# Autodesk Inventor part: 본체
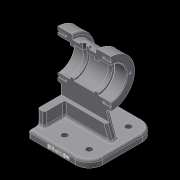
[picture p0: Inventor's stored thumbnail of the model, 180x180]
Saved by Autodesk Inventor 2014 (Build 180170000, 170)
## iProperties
Created: 2020-06
Part Number: 본체
Material: Generic
Document SubType Name: Modeling
Designer: kh
Density: 1 g/cm^3
Appearance: Default
Author: kh
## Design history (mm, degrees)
sketch "Sketch1"
  geometry: 1 further point
sketch "Sketch2"
  geometry: L1 (-45, 49)-(45, 49); L2 (45, 49)-(45, -49); L3 (45, -49)-(-45, -49); L4 (-45, -49)-(-45, 49); L5 (-45, 49)-(45, -49); L6 (45, 49)-(-45, -49); 1 further point
  constraints: 12 end point, 2 midpoint, 2 parallel, 1 horizontal, 1 perpendicular
  dimensions: "d0" = 90 distance of L1.start L1.end; "d1" = 98 distance of L1.end L2.end
extrude "Extrusion1" new body sketch "Sketch2" distance "d2" = 10; taper "d3" = 0 deg
sketch "Sketch4"
  geometry: L1 (-50, 105)-(-50, 70); L2 (-50, 70)-(28, 70); L3 (28, 70)-(28, 105); L4 (28, 105)-(6, 105); L5 (6, 105)-(6, 98.5); L6 (6, 98.5)-(-28, 98.5); L7 (-28, 98.5)-(-28, 105); L8 (-28, 105)-(-50, 105); L9 (-45, -10)-(45, -10) reference; 3 further points
  constraints: 16 end point, 4 parallel, 2 midpoint, 1 horizontal alignment, 1 perpendicular, 1 vertical
  dimensions: "d5" = 78 distance of L3.end L1.start; "d9" = 22 distance of L7.end L1.start; "d10" = 22 distance of L3.end L4.end; "d11" = 5 horizontal distance of L9.start L1.end; "d12" = 70 diameter of L8 L2; "d13" = 57 diameter of L6 L2; "d14" = 80 vertical distance of L9.end L2.end
revolve "Revolution1" sketch "Sketch4" stored, may be unused: angle "d15" = 90 deg
sketch "Sketch5"
  geometry: L1 (-45, 61.811)-(-45, 0); L2 (10.503, 61.811)-(33, 0); L3 (-45, 0)-(45, 0) reference; L4 (-45, 61.811)-(10.503, 61.811); L5 (-45, 0)-(33, 0); L6 (-50, 35)-(-50, 105) reference; 1 further point
  constraints: 8 end point, 2 point on line, 1 parallel, 1 perpendicular, 1 vertical
  dimensions: "d16" = 70 deg angle of L2 L3; "d17" = 5 distance from line of L1.end L6; "d18" = 12 distance of L3.end L2.end
extrude "Extrusion2" join sketch "Sketch5" stored distance "d19" = 10; taper "d20" = 0 deg
sketch "Sketch6"
  geometry: L1 (-45, 35)-(-35, 35); L2 (-35, 35)-(-35, -35); L3 (-35, -35)-(-45, -35); L4 (-45, -35)-(-45, 35); 3 further points
  constraints: 8 end point, 2 parallel, 1 horizontal, 1 horizontal alignment, 1 midpoint, 1 perpendicular, 1 vertical alignment
  dimensions: "d21" = 70 distance between parallel lines of L3 L1; "d22" = 10 horizontal distance of point (-45, 49) L1.end
extrude "Extrusion3" join sketch "Sketch6" distance "d23" = 70; taper "d24" = 0 deg
sketch "Sketch7"
  geometry: L1 (45, 49)-(45, -49) reference; 8 further points
  constraints: 3 horizontal alignment, 2 vertical alignment, 1 midpoint
  dimensions: "d25" = 36 distance of point (25, 29) point (-11, 29); "d26" = 70 horizontal distance of point (25, 29) point (-45, 49); "d27" = 58 distance of point (25, -29) point (25, 29)
hole "Hole1" sketch "Sketch7" at (-11, 29), (25, 29), (25, -29), (-11, -29) diameter "d28" = 9; stored, may be unused: countersink angle "d32" = 90 deg, drill point angle "d34" = 118 deg; dims "d29" = 6, "d30" = 4, "d31" = 2, "d33" = 8
sketch "Sketch8"
  geometry: L1 (-50, 70)-(28, 70); L2 (-50, 35)-(-50, 105) reference; L3 (28, 35)-(28, 105) reference; L4 (-50, 70)-(-50, 93.5); L5 (-50, 93.5)-(-32, 93.5); L6 (-32, 93.5)-(-32, 90); L7 (-32, 90)-(-26, 90); L8 (-26, 90)-(-26, 93); L9 (-26, 93)-(4, 93); L10 (4, 93)-(4, 90); L11 (4, 90)-(10, 90); L12 (10, 90)-(10, 93.5); L13 (10, 93.5)-(28, 93.5); L14 (28, 70)-(28, 93.5); 4 further points
  constraints: 24 end point, 6 parallel, 5 midpoint, 4 perpendicular, 3 point on line, 1 horizontal, 1 horizontal alignment
  dimensions: "d35" = 47 diameter of L5 L1; "d36" = 40 diameter of L7 L1; "d37" = 18 distance of L4.end L5.end; "d38" = 6 distance of L6.end L7.end; "d39" = 30 distance of L8.end L9.end; "d40" = 18 distance of L12.end L13.end; "d41" = 47 diameter of L13 L1; "d42" = 46 diameter of L9 L1
revolve "Revolution2" sketch "Sketch8" stored, may be unused: angle "d43" = 90 deg
workplane "Work Plane2"
sketch "Sketch9"
  geometry: L1 (-50, -35)-(-50, 35) reference; C1 r 6 at (-11, 0); 2 further points
  constraints: 1 centre point, 1 coincident, 1 horizontal alignment
  dimensions: "d45" = 39 distance from line of point (-11, 0) L1; "d46" = 12 diameter of C1
extrude "Extrusion4" join sketch "Sketch9" stored distance "d47" = 70; taper "d48" = 0 deg
hole "Hole2" diameter "d51" = 5.188; stored, may be unused: countersink angle "d55" = 90 deg, drill point angle "d57" = 118 deg; dims "d49" = 10, "d50" = 10, "d52" = 6, "d53" = 4, "d54" = 2, "d56" = 8
sketch "Sketch10"
  geometry: C1 r 23.5 at (0, 0) reference; 2 further points
  constraints: 1 vertical alignment
  dimensions: "d59" = 28.5 distance of C1.centre point (0, 28.5)
hole "Hole3" sketch "Sketch10" at (0, 28.5) diameter "d60" = 3.242; stored, may be unused: countersink angle "d64" = 90 deg, drill point angle "d66" = 118 deg; dims "d61" = 10, "d62" = 4, "d63" = 2, "d65" = 12
pattern_circular "Circular Pattern1" dims angle "d68" = 360 deg
workplane "Work Plane3"
mirror "Mirror1"
fillet "Fillet1" dims "d70" = 3
fillet "Fillet2" dims "d71" = 3
fillet "Fillet5" dims "d74" = 3
sketch "Sketch11"
  geometry: L1 (-3, 7)-(-3, 0) reference; 3 further points
  constraints: 1 other
  dimensions: "d75" = 4 vertical distance of point (0, 0) point (42, 4); "d76" = 45 distance from line of point (42, 4) L1
emboss "Emboss1" sketch "Sketch11" dims "d0" = 90, "d1" = 98, "d15" = 90 deg, "d77" = 0.5, "d78" = 0
chamfer "Chamfer1" distance "d79" = 1; stored, may be unused: second distance "d80" = 2, angle "d81" = 45 deg
fillet "Fillet6" dims "d82" = 20, "d83" = 3
fillet "Fillet7" dims "d84" = 3
fillet "Fillet8" dims "d85" = 3
fillet "Fillet9" dims "d86" = 0.3
sketch "Sketch12"
  geometry: L1 (-60.783, 110.8)-(64.983, 110.8); L2 (64.983, 110.8)-(64.983, 20.217); L3 (64.983, 20.217)-(-60.783, 20.217); L4 (-60.783, 20.217)-(-60.783, 110.8); 1 further point
  constraints: 8 end point, 2 parallel, 1 horizontal, 1 perpendicular
extrude "Extrusion5" cut sketch "Sketch12" distance "d87" = 70; taper "d88" = 0 deg
body "Solid1"
other parameters: "d44" = -111.5
